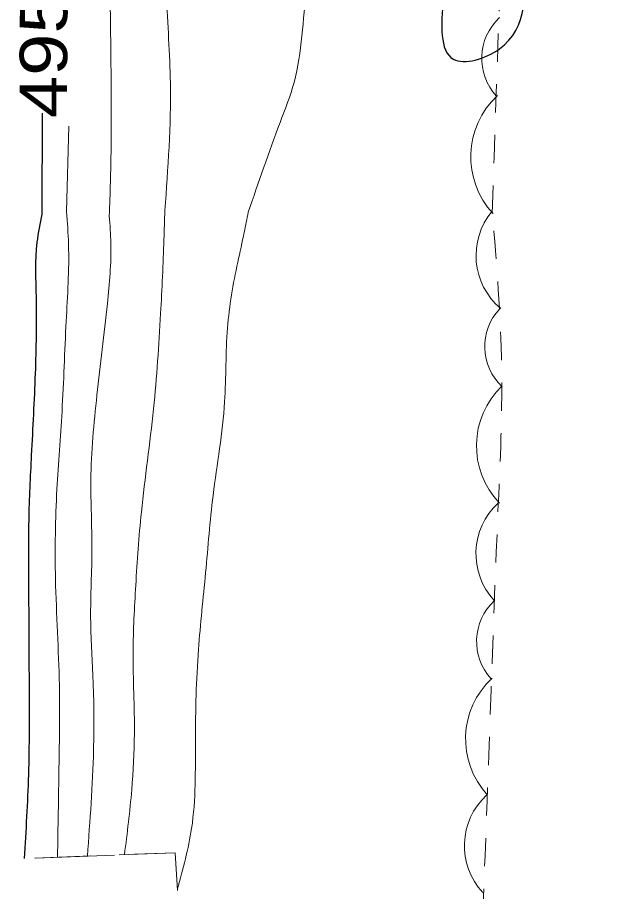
# Model space of a CAD drawing. Extents: x 2362213 to 2366494, y 6968794 to 6978110.
# Drawn here: x 2364529.6 to 2364589.7, y 6971006.4 to 6971094.9 of the extents above; entities that cross this region are included whole.
import ezdxf
from ezdxf.enums import TextEntityAlignment as Align

# ---------------------------------------------------------------- set-up
doc = ezdxf.new("R2010")
doc.units = 0
doc.header["$LTSCALE"] = 1.9
doc.linetypes.add('MEDIUM_DASHED', pattern=[4.5, 3, -1.5])
doc.linetypes.add('SHORT_DASHED', pattern=[2.7, 1.5, -1.2])
for name, color, linetype, lineweight in [('29', 7, 'Continuous', 13), ('31', 7, 'Continuous', 25), ('35', 7, 'Continuous', 13), ('8', 7, 'Continuous', 13)]:
    doc.layers.add(name, color=color, linetype=linetype, lineweight=lineweight)

msp = doc.modelspace()

# ---------------------------------------------------------------- linework, layer by layer
at = {"layer": '29'}
for centre, radius, start, end in [((2364582.252, 6971090.77), 5.637, 132.85786, 222.85786), ((2364583.966, 6971080.802), 8.46, 132.85786, 222.85786), ((2364583.031, 6971070.796), 6.989, 140.06883, 230.06883), ((2364582.503, 6971061.578), 5.585, 136.72485, 226.72485), ((2364584.466, 6971051.533), 8.382, 133.82712, 223.82712), ((2364583.02, 6971040.592), 6.989, 132.75903, 222.75903), ((2364581.683, 6971031.721), 5.585, 132.75903, 222.75903), ((2364583.364, 6971021.842), 8.382, 132.75903, 222.75903), ((2364581.857, 6971011.012), 6.989, 132.73125, 222.73125)]:
    msp.add_arc(centre, radius, start, end, dxfattribs=at)
at = {"layer": '29', "linetype": 'SHORT_DASHED'}
for points in [[(2364577.69, 6971075.047), (2364579.29, 6971120.184), (2364580.17, 6971165.405), (2364577.6, 6971211.582), (2364578.72, 6971259.895), (2364580.684, 6971315.076), (2364583.342, 6971362.574), (2364582.348, 6971418.658), (2364583.179, 6971469.038), (2364581.378, 6971508.953), (2364580.351, 6971579.056), (2364585.114, 6971632.334), (2364584.87, 6971699.884), (2364582.326, 6971774.844), (2364585.046, 6971827.382), (2364586.299, 6971874.516), (2364587.992, 6971886.814), (2364587.862, 6971909.833), (2364589.094, 6971931.726), (2364587.912, 6971940.364)], [(2364482.797, 6970610.891), (2364491.851, 6970614.577), (2364499.181, 6970623.098), (2364502.659, 6970639.061), (2364521.349, 6970653.91), (2364537.929, 6970655.978), (2364553.09, 6970664.433), (2364563.76, 6970701.216), (2364580.367, 6970716.205), (2364615.915, 6970746.135), (2364657.45, 6970773.112), (2364687.332, 6970804.488), (2364698.188, 6970835.412), (2364668.499, 6970850.93), (2364633.617, 6970851.998), (2364600.666, 6970867.696), (2364582.677, 6970907.316), (2364575.266, 6970951.688), (2364576.447, 6970998.791), (2364578.21, 6971043.58), (2364578.628, 6971059.544), (2364577.699, 6971075.187)]]:
    msp.add_spline(points, degree=3, dxfattribs=at)
at = {"layer": '31'}
msp.add_line((2364532.111, 6971085.223), (2364532.078, 6971075.002), dxfattribs=at)
for points in [[(2364573.196, 6971117.596), (2364573.263, 6971106.315), (2364572.695, 6971096.69), (2364573.742, 6971090.7), (2364578.411, 6971091.734), (2364580.949, 6971101.378)], [(2364532.078, 6971075.002), (2364531.565, 6971072.147), (2364531.479, 6971066.546), (2364531.392, 6971058.854), (2364531.001, 6971050.581), (2364530.734, 6971043.978), (2364530.723, 6971036.727), (2364530.774, 6971027.118), (2364530.709, 6971018.207), (2364530.271, 6971009.721)]]:
    msp.add_spline(points, degree=3, dxfattribs=at)
at = {"layer": '35'}
msp.add_line((2364534.784, 6971083.918), (2364534.566, 6971075.266), dxfattribs=at)
for points in [[(2364534.659, 6971711.347), (2364534.622, 6971704.746), (2364534.491, 6971695.395), (2364534.586, 6971687.555), (2364534.183, 6971674.201), (2364533.782, 6971664.846), (2364532.952, 6971651.128), (2364532.501, 6971640.733), (2364532.674, 6971631.014), (2364532.769, 6971615.725), (2364532.834, 6971599.474), (2364533.434, 6971585.81), (2364534.16, 6971570.465), (2364534.443, 6971548.106), (2364534.623, 6971534.529), (2364534.929, 6971518.151), (2364535.056, 6971498.48), (2364534.778, 6971485.648), (2364535.317, 6971471.072), (2364535.799, 6971456.165), (2364536.105, 6971438.708), (2364536.668, 6971420.553), (2364536.959, 6971396.355), (2364536.922, 6971379.162), (2364537.234, 6971365.325), (2364537.314, 6971346.385), (2364537.015, 6971321.091), (2364536.777, 6971303.068), (2364536.531, 6971280.554), (2364534.865, 6971251.777), (2364534.309, 6971237.671), (2364533.822, 6971218.466), (2364533.54, 6971190.382), (2364534.519, 6971174.72), (2364535.261, 6971162.997), (2364537.111, 6971150.373), (2364537.276, 6971134.115), (2364537.853, 6971121.77), (2364538.344, 6971112.254), (2364538.866, 6971101.547), (2364539.053, 6971091.31), (2364539.085, 6971081.658), (2364538.9, 6971074.807)], [(2364538.72, 6971711.256), (2364538.714, 6971707.645), (2364538.506, 6971700.133), (2364538.624, 6971689.864), (2364538.106, 6971675.918), (2364537.183, 6971663.659), (2364536.827, 6971652.705), (2364536.395, 6971640.33), (2364536.047, 6971623.346), (2364536.259, 6971609.528), (2364536.61, 6971592.559), (2364537.343, 6971576.486), (2364537.905, 6971563.731), (2364538.722, 6971549.328), (2364538.918, 6971540.27), (2364538.905, 6971528.019), (2364538.915, 6971509.148), (2364538.925, 6971494.348), (2364539.2, 6971478.119), (2364539.916, 6971463.856), (2364540.78, 6971448.723), (2364540.884, 6971438.874), (2364540.815, 6971427.172), (2364541.097, 6971412.374), (2364541.938, 6971396.542), (2364542.166, 6971380.972), (2364541.982, 6971362.49), (2364541.961, 6971346.859), (2364541.87, 6971331.198), (2364541.958, 6971318.878), (2364541.866, 6971300.116), (2364541.373, 6971283.631), (2364540.207, 6971269.429), (2364538.758, 6971255.724), (2364538.084, 6971239.358), (2364537.418, 6971219.95), (2364536.894, 6971198.314), (2364537.51, 6971183.009), (2364539.204, 6971171.054), (2364540.746, 6971159.339), (2364542.162, 6971148.261), (2364542.971, 6971137.929), (2364543.524, 6971123.953), (2364543.735, 6971116.495), (2364544.569, 6971104.492), (2364544.708, 6971097.254), (2364545.084, 6971088.257), (2364544.526, 6971075.361)], [(2364542.072, 6971711.187), (2364542.205, 6971707.709), (2364542.183, 6971701.648), (2364542.02, 6971692.466), (2364542.138, 6971683.267), (2364542.714, 6971675.242), (2364542.934, 6971665.844), (2364542.717, 6971653.941), (2364542.556, 6971643.499), (2364542.06, 6971627.404), (2364541.628, 6971612.868), (2364542.43, 6971595.816), (2364542.907, 6971575.159), (2364544.177, 6971560.501), (2364544.526, 6971547.952), (2364544.74, 6971532.875), (2364544.927, 6971520.575), (2364545.357, 6971504.829), (2364546.353, 6971489.518), (2364546.922, 6971474.872), (2364548.75, 6971462.56), (2364549.651, 6971452.817), (2364549.64, 6971436.286), (2364549.682, 6971419.297), (2364549.892, 6971407.737), (2364549.925, 6971401.088), (2364549.973, 6971386.597), (2364550.139, 6971372.319), (2364550.567, 6971359.851), (2364551.663, 6971349.752), (2364552.419, 6971343.908), (2364552.9, 6971335.373), (2364552.63, 6971328.031), (2364551.996, 6971314.823), (2364551.49, 6971301.718), (2364551.166, 6971294.834), (2364550.298, 6971287.376), (2364548.521, 6971276.538), (2364546.285, 6971267.706), (2364545.619, 6971258.92), (2364546.489, 6971246.317), (2364546.173, 6971233.274), (2364545.764, 6971219.539), (2364546.984, 6971213.201), (2364548.563, 6971198.665), (2364548.16, 6971189.491), (2364548.457, 6971180.393), (2364550.385, 6971174.241), (2364553.53, 6971166.241), (2364554.269, 6971161.128), (2364556.051, 6971152.574), (2364556.307, 6971150.867), (2364556.954, 6971139.672), (2364556.528, 6971129.758), (2364556.654, 6971118.618), (2364559.794, 6971106.087), (2364558.902, 6971097.869), (2364557.613, 6971088.336), (2364556.191, 6971084.271), (2364552.978, 6971075.191)], [(2364534.566, 6971075.266), (2364534.768, 6971071.928), (2364534.532, 6971064.145), (2364534.109, 6971055), (2364533.594, 6971047.146), (2364533.45, 6971038.033), (2364533.843, 6971027.287), (2364533.802, 6971018.936), (2364533.659, 6971009.854)], [(2364544.526, 6971075.361), (2364544.434, 6971072.44), (2364544.096, 6971064.926), (2364543.378, 6971055.268), (2364542.147, 6971044.797), (2364541.578, 6971037.4), (2364541.312, 6971030.618), (2364541.441, 6971022.359), (2364541.175, 6971016.695), (2364540.437, 6971010.108)], [(2364552.978, 6971075.191), (2364552.568, 6971073.157), (2364551.907, 6971070.121), (2364550.87, 6971063.471), (2364550.581, 6971055.997), (2364549.412, 6971046.496), (2364548.656, 6971038.688), (2364547.93, 6971030.881), (2364547.618, 6971021.658), (2364547.233, 6971012.763), (2364545.791, 6971006.63)], [(2364538.9, 6971074.807), (2364539.057, 6971072.029), (2364538.705, 6971065.945), (2364537.653, 6971056.654), (2364537.035, 6971048.068), (2364537.141, 6971041.109), (2364537.009, 6971034.037), (2364537.245, 6971028.08), (2364537.305, 6971020.73), (2364536.678, 6971009.962)]]:
    msp.add_spline(points, degree=3, dxfattribs=at)
at = {"layer": '8'}
msp.add_line((2364539.437, 6971010.069), (2364531.44, 6971009.762), dxfattribs=at)
at = {"layer": '8', "linetype": 'MEDIUM_DASHED'}
msp.add_lwpolyline([(2364546.775, 6970989.448), (2364545.586, 6971010.307), (2364482.396, 6971007.895)], dxfattribs=at)
at = {"layer": '8'}
msp.add_lwpolyline([(2364545.803, 6971006.47), (2364545.586, 6971010.307), (2364541.437, 6971010.148)], dxfattribs=at)

# ---------------------------------------------------------------- texts
at = {"layer": '31', "width": 1.2}
msp.add_text(' 495 ', height=4.8, rotation=89.912, dxfattribs=at).set_placement((2364534.632, 6971091.139), align=Align.CENTER)

doc.saveas('drawing.dxf')
